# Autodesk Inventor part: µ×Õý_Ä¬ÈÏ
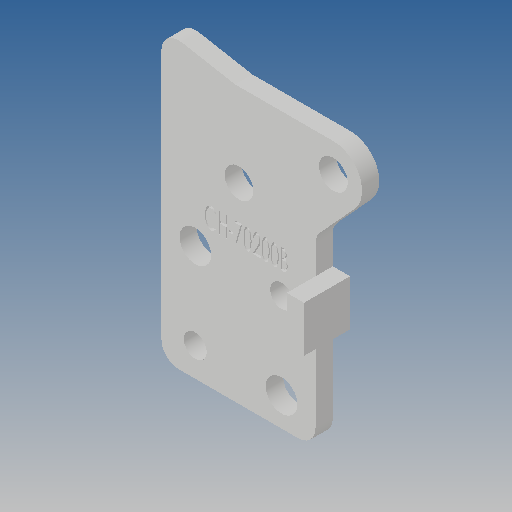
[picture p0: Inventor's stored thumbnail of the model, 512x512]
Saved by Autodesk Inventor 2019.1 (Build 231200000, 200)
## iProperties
Created: 2012-10
Part Number: µ×Õý_Ä¬ÈÏ
Material: Ogólny
Document SubType Name: Modeling
Designer: CADENGINEERING4
Density: 1 g/cm^3
Appearance: Domyślna
Author: CADENGINEERING4
Revision Number: ÈÎºÎ
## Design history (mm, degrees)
feature "NONE"
node "Bryła1"
